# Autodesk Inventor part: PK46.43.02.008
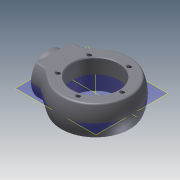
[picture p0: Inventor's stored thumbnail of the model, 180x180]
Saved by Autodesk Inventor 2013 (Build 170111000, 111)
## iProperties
Shininess: 20.0
Length Units: 11269
Angle Units: 11279
Time Units: 11290
Mass Units: 11283
Length Display Precision: 3
Angle Display Precision: 2
Created: 2001-08
Part Number: PK46.43.02.008
Material: Steel, Mild
Document SubType Name: Modeling
Designer: SOleg
Density: 7.86 g/cm^3
Density: 0.0
Volumn: 0.0
Area: 0.0
PropertySet Name: Model Information
Control State: 0
Master: False
Checked Out: True
Checked Out Date: 2008-10-09
Last Check In Date: 2008-10-09
Author: SOleg
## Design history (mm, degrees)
node "WorkPlane3"
node "WorkPlane1"
node "WorkPlane4"
sketch "Sketch3"
  geometry: L1 (-121.126, -62.5)-(-121.126, 0); L2 (-81.126, -62.5)-(-121.126, -62.5); L3 (-45.862, -83.69)-(-75.862, -64.069); L4 (-121.126, 0)-(108.874, 0); L5 (-121.126, 0)-(108.874, 0); A1 r 9.617 centre (-81.126, -72.117) between (-75.862, -64.069) and (-81.126, -62.5); A2 r 100 centre (8.874, 0) between (-45.862, -83.69) and (108.874, 0)
  constraints: 10 end point, 4 point on circle, 3 tangent, 2 centre point, 2 horizontal, 1 vertical, 1 other
  dimensions: "d2" = 130 horizontal distance of A2.centre L1.start; "d4" = 0 vertical distance of A2.centre L4.end; "d6" = 100 radius of A2; "d8" = 40 distance of L2.start L1.start; "d10" = 62.5 distance of L1.start L1.end; "d12" = 30 horizontal distance of L3.start L3.end
revolve "RevolutionAngle1" sketch "Sketch3" stored, may be unused: angle "d13" = 360 deg
sketch "Sketch4"
  geometry: L1 (-108.874, 140)-(-108.874, 40); L2 (141.126, 140)-(-108.874, 140); L3 (141.126, 55)-(141.126, 140); L4 (-108.874, 40)-(126.126, 40); L5 (-108.874, -140)-(-108.874, -40); L6 (141.126, -140)-(-108.874, -140); L7 (141.126, -55)-(141.126, -140); L8 (-108.874, -40)-(126.126, -40); C1 r 62.5 at (121.126, 0); A1 r 15 centre (126.126, 55) between (126.126, 40) and (141.126, 55); A2 r 15 centre (126.126, -55) between (141.126, -55) and (126.126, -40)
  constraints: 16 end point, 4 horizontal, 4 point on circle, 4 tangent, 3 centre point, 3 vertical, 1 collinear
  dimensions: "d16" = 80 distance of L5.end L1.end; "d18" = 15 radius of A1; "d20" = 100 distance of L1.start L1.end; "d22" = 100 distance of L5.start L5.end; "d24" = 250 horizontal distance of L5.end L2.start; "d26" = 250 distance of L6.start L5.start; "d28" = 20 horizontal distance of L3.start C1.centre
extrude "ExtrusionMidplane1" cut sketch "Sketch4" stored distance "d29" = 200; taper "d30" = 0 deg
sketch "Sketch5"
  geometry: C1 r 26 at (0, 0)
  constraints: 1 centre point
  dimensions: "d32" = 52 diameter of C1
extrude "ExtrusionMidplane2" cut sketch "Sketch5" stored distance "d33" = 53; taper "d34" = 0 deg
revolve "RevolutionAngle3" stored, may be unused: angle "d40" = 360 deg
revolve "RevolutionAngle4" stored, may be unused: angle "d49" = 360 deg
sketch "Sketch8"
  geometry: C1 r 2 at (72.126, 0); C2 r 30 at (121.126, 0)
  constraints: 2 centre point
  dimensions: "d51" = 49 distance of C1.centre C2.centre; "d53" = 4 diameter of C1
extrude "ExtrusionMidplane3" cut sketch "Sketch8" stored distance "d54" = 150; taper "d55" = 0 deg
sketch "Эскиз12"
  geometry: L1 (130, -30)-(130, 30) reference; L2 (115, -19.365)-(115, -19.365) reference; L3 (115, 19.365)-(115, 19.365) reference; L4 (126.36, 40)-(126.36, -40) reference; A1 r 88.318 centre (0, 0) between (51.999, 71.387) and (51.999, -71.387) reference; 3 further points
  dimensions: "d85" = 130 distance from line of L1 point (0, 0); "d86" = 0 distance of A1.centre point (0, 0)
hole "Отверстие2" sketch "Эскиз12" diameter "d87" = 125; stored, may be unused: countersink angle "d91" = 82 deg, drill point angle "d93" = 118 deg; dims "d88" = 6, "d89" = 129, "d90" = 2, "d92" = 40
node "РабПлоскость4"
mirror "ЗеркОтобр1"
node "РабОсь4"
sketch "Эскиз13"
  geometry: L1 (-176, 0)-(146, 0) reference; L2 (-130, 30)-(-130, -30) reference; C1 r 64.5 at (0, 0) reference; 1 further point
  dimensions: "d100" = 0 distance from line of point (72.5, 0) L1; "d101" = 72.5 distance of C1.centre point (72.5, 0)
hole "Отверстие3" sketch "Эскиз13" diameter "d102" = 10; stored, may be unused: countersink angle "d106" = 82 deg, drill point angle "d108" = 118 deg; dims "d103" = 6, "d104" = 13.2, "d105" = 2, "d107" = 16
feature "Резьба2" dims "d109" = 10, "d110" = 0
node "РабОсь5"
pattern_circular "Круговой массив2" dims angle "d113" = 360 deg
feature "Резьба3" dims "d114" = 10, "d115" = 0
feature "Резьба4" dims "d116" = 10, "d117" = 0
feature "Резьба5" dims "d118" = 10, "d119" = 0
feature "Резьба6" dims "d120" = 10, "d121" = 0
mirror "ЗеркОтобр2"
feature "Резьба7" dims "d122" = 10, "d123" = 0
feature "Резьба8" dims "d124" = 10, "d125" = 0
feature "Резьба9" dims "d126" = 10, "d127" = 0
feature "Резьба10" dims "d128" = 10, "d129" = 0
feature "Резьба11" dims "d130" = 10, "d131" = 0
feature "Резьба12" dims "d132" = 10, "d133" = 0
sketch "Эскиз14"
  geometry: C1 r 26 at (35, -19.365); A1 r 40 centre (35, -19.365) between (70, 0) and (0, 0) reference
  constraints: 1 centre point, 1 coincident
  dimensions: "d134" = 52 diameter of C1
extrude "Выдавливание4" cut sketch "Эскиз14" distance "d135" = 37; taper "d136" = 0 deg
body "Solid1"
fillet "Fillet1" dims "d69" = 5
fillet "Fillet2" dims "d70" = 5
node "WorkPlane2"
sketch "Sketch6"
  geometry: L1 (89.626, 0)-(94.626, 0); L2 (94.626, 25)-(89.626, 0); L3 (94.626, 0)-(94.626, 25); L4 (-192.376, 0)-(192.376, 0); L5 (94.626, 0)-(94.626, 1); L6 (-192.376, 0)-(192.376, 0)
  constraints: 12 end point, 2 collinear, 1 horizontal
  dimensions: "d37" = 25 distance of L1.end L2.start; "d39" = 5 distance of L1.start L1.end
sketch "Sketch7"
  geometry: L1 (-117.487, 40)-(-106.126, 40); L2 (-121.126, 30)-(-117.487, 40); L3 (-121.126, 62.5)-(-121.126, 30); L4 (-106.126, 62.5)-(-121.126, 62.5); L5 (-106.126, 40)-(-106.126, 62.5); L6 (-163.686, 0)-(151.433, 0)
  constraints: 12 end point, 2 horizontal, 2 vertical
  dimensions: "d42" = 15 distance of L4.start L3.start; "d44" = 20 deg angle of L2 L3; "d46" = 32.5 distance of L3.start L2.start; "d48" = 22.5 distance of L1.end L4.start
node "Спроецированная петля1"
other parameters: "d3" = 0 (derived), "d9" = 62.5 (derived), "d14" = 0, "d17" = 15 (derived), "d31" = 52 (derived), "d35" = 0, "d36" = 25 (derived), "d38" = 5 (derived), "d41" = 15 (derived), "d43" = 20 deg (derived), "d45" = 32.5 (derived), "d47" = 22.5 (derived), "d50" = 49 (derived), "d52" = 4 (derived), "d56" = 5 (derived), "d58" = 5 (derived), "d60" = 5 (derived), "d62" = 5 (derived), "d64" = 57.5 (derived)
